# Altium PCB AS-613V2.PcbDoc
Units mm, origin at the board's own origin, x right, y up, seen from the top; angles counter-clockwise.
Board outline 32 x 30 mm, 4 copper layers (Top Layer, Layer 1, Layer 2, Bottom Layer), stack 1.18 mm thick; 70 components, 43 nets, 483 pads, 357 vias.
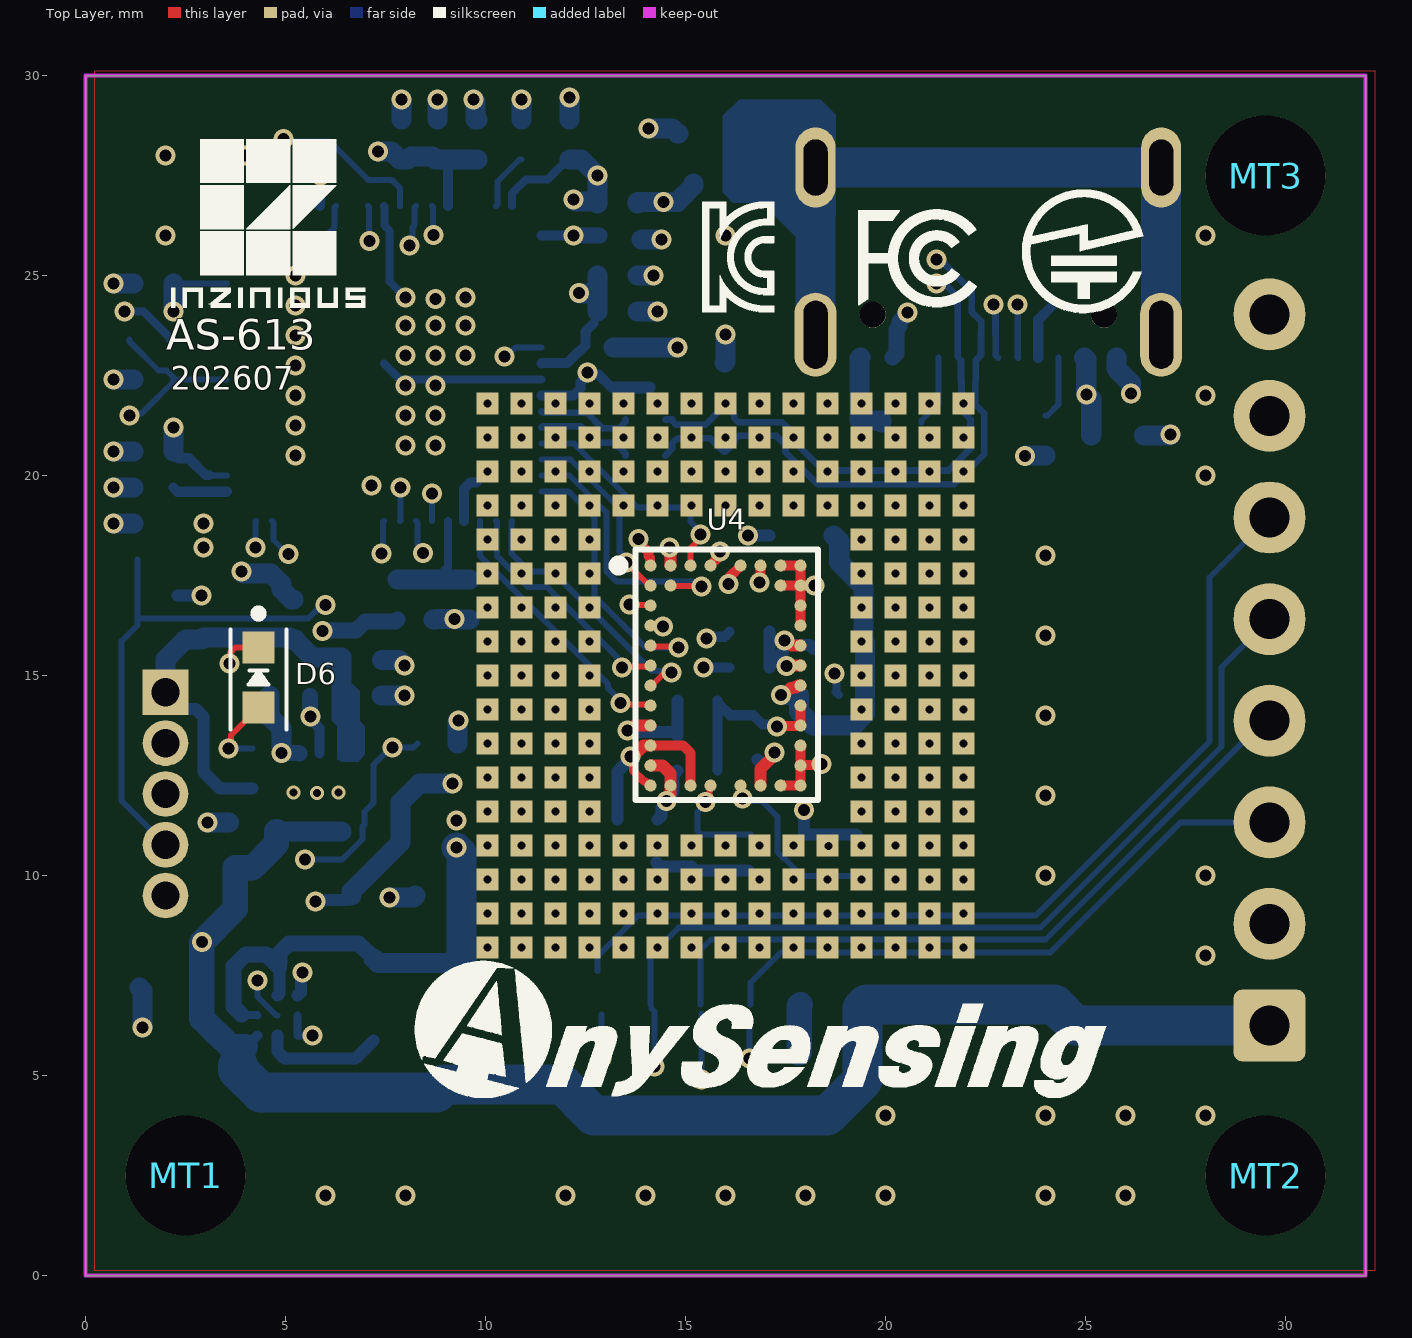
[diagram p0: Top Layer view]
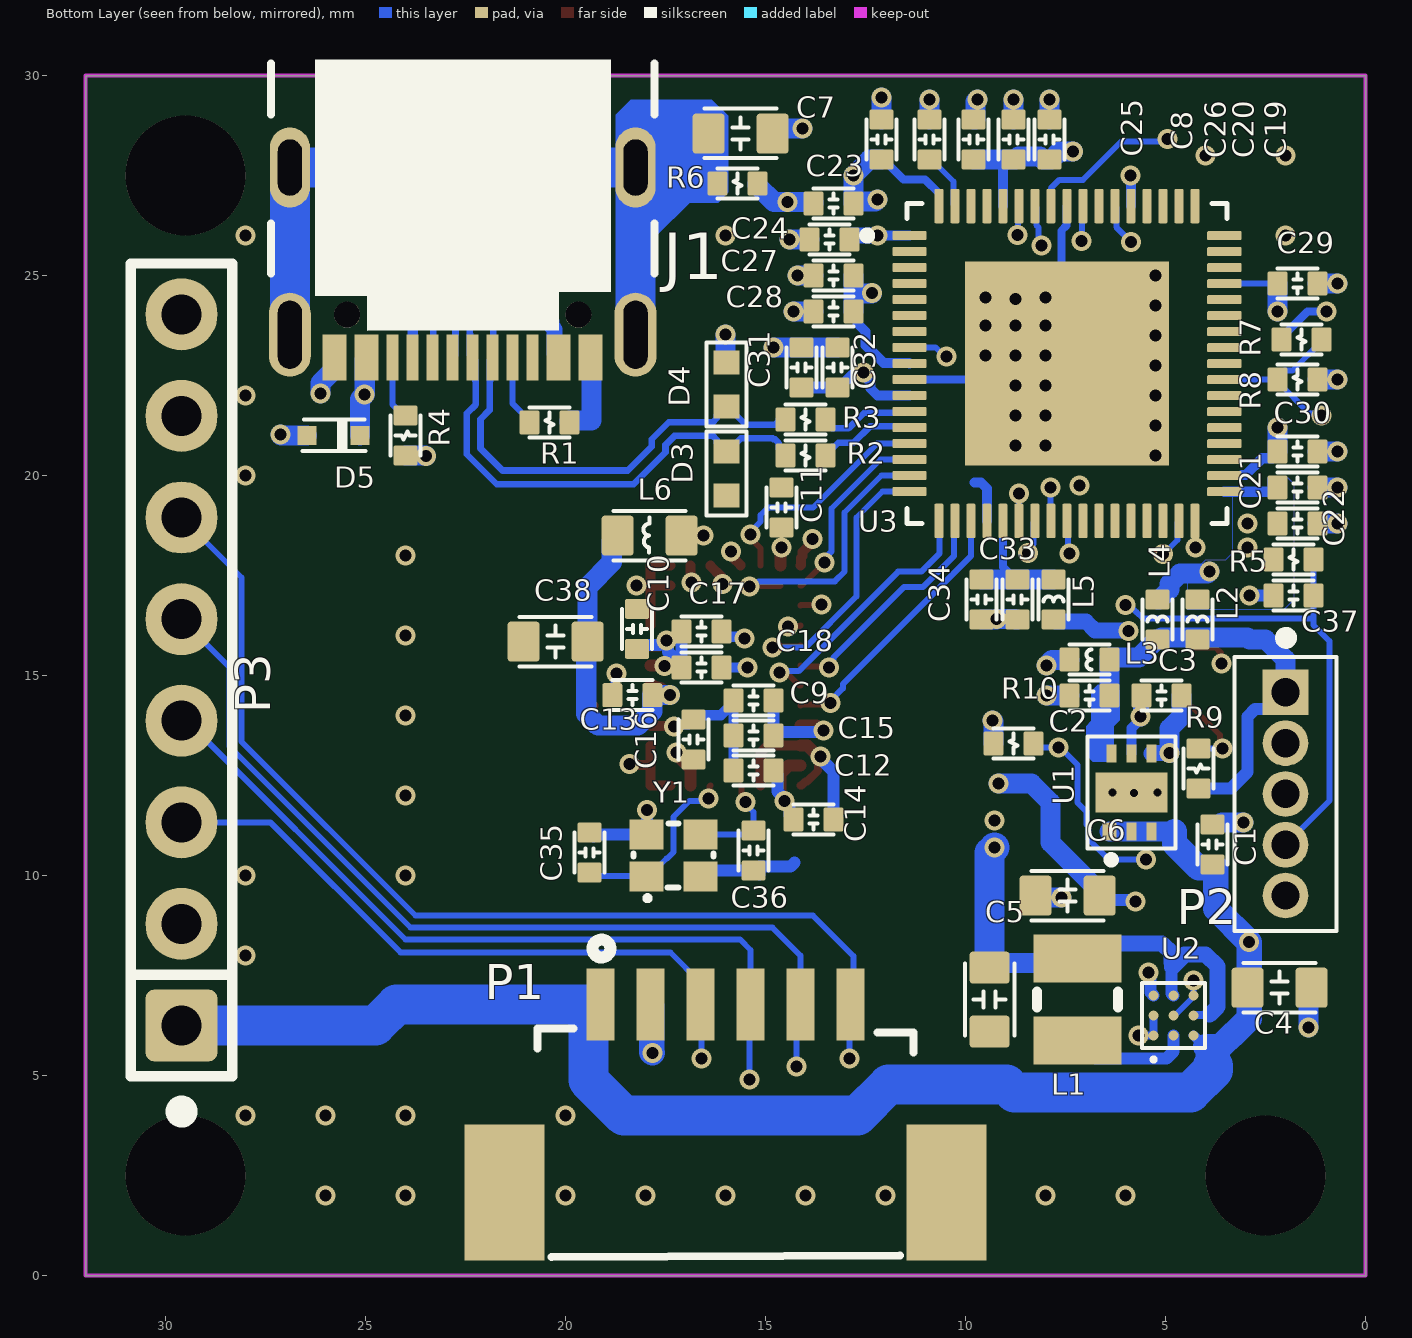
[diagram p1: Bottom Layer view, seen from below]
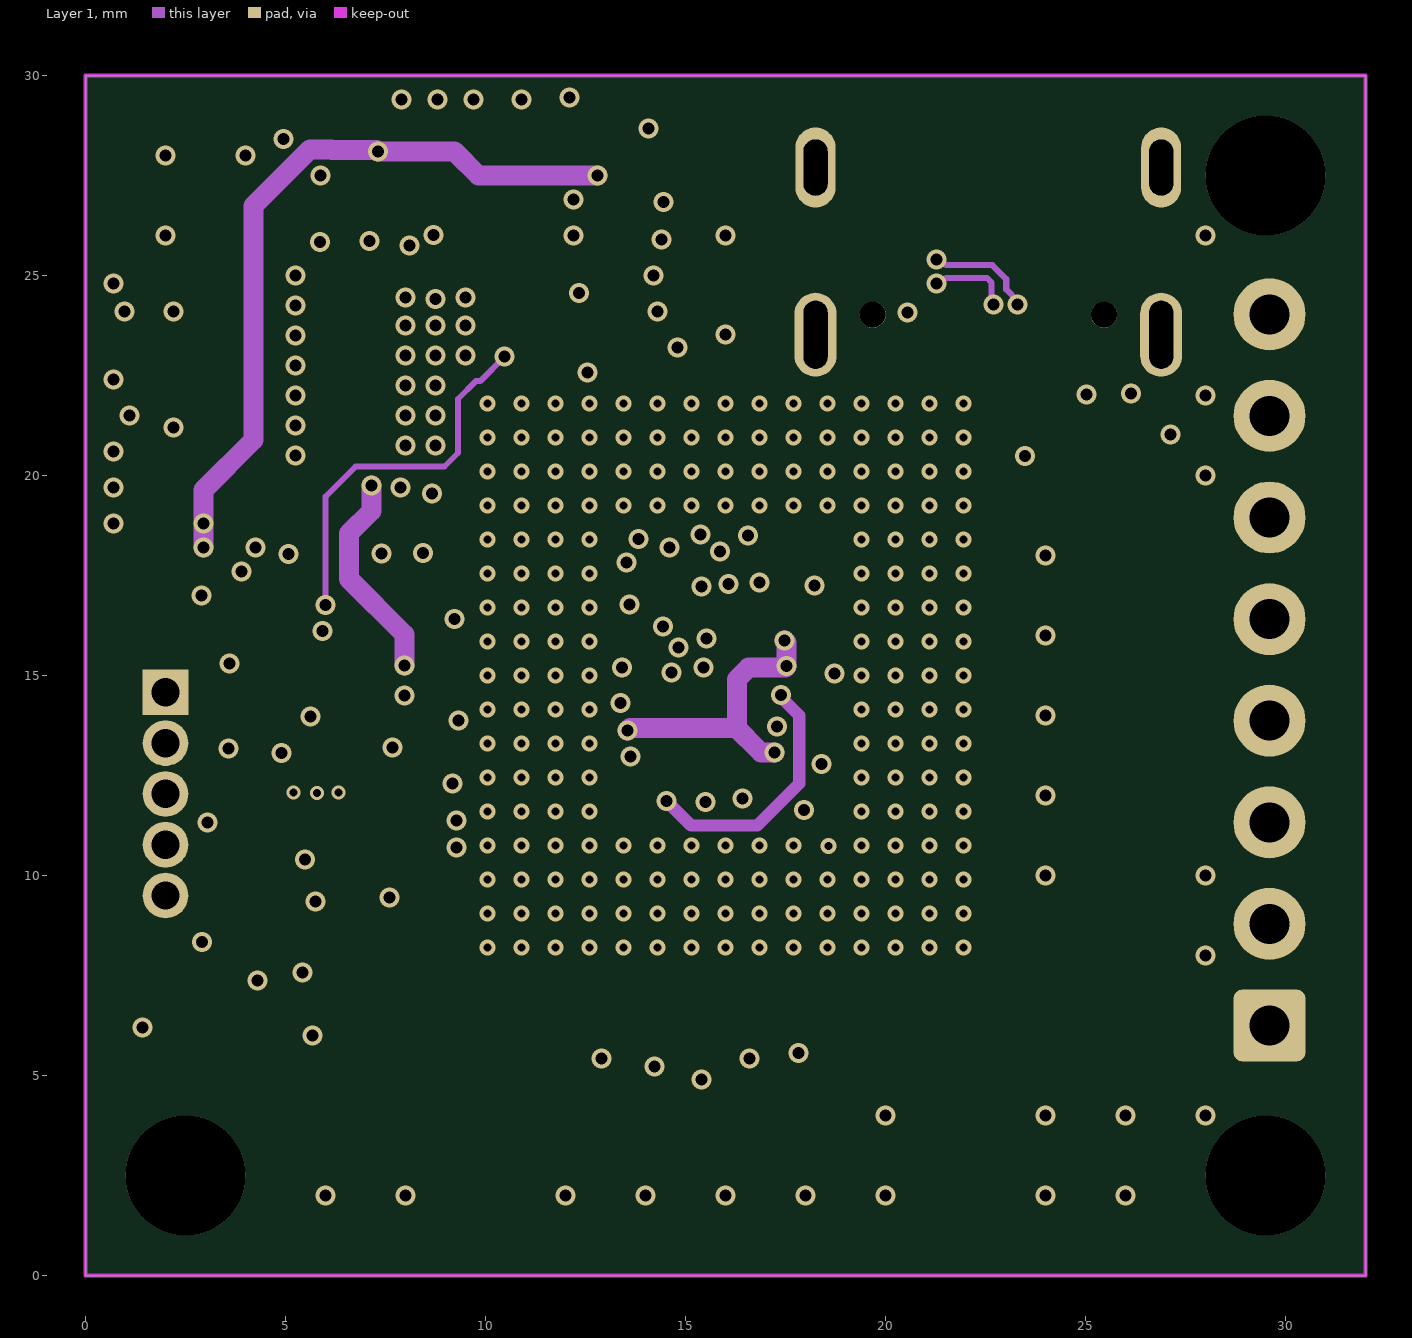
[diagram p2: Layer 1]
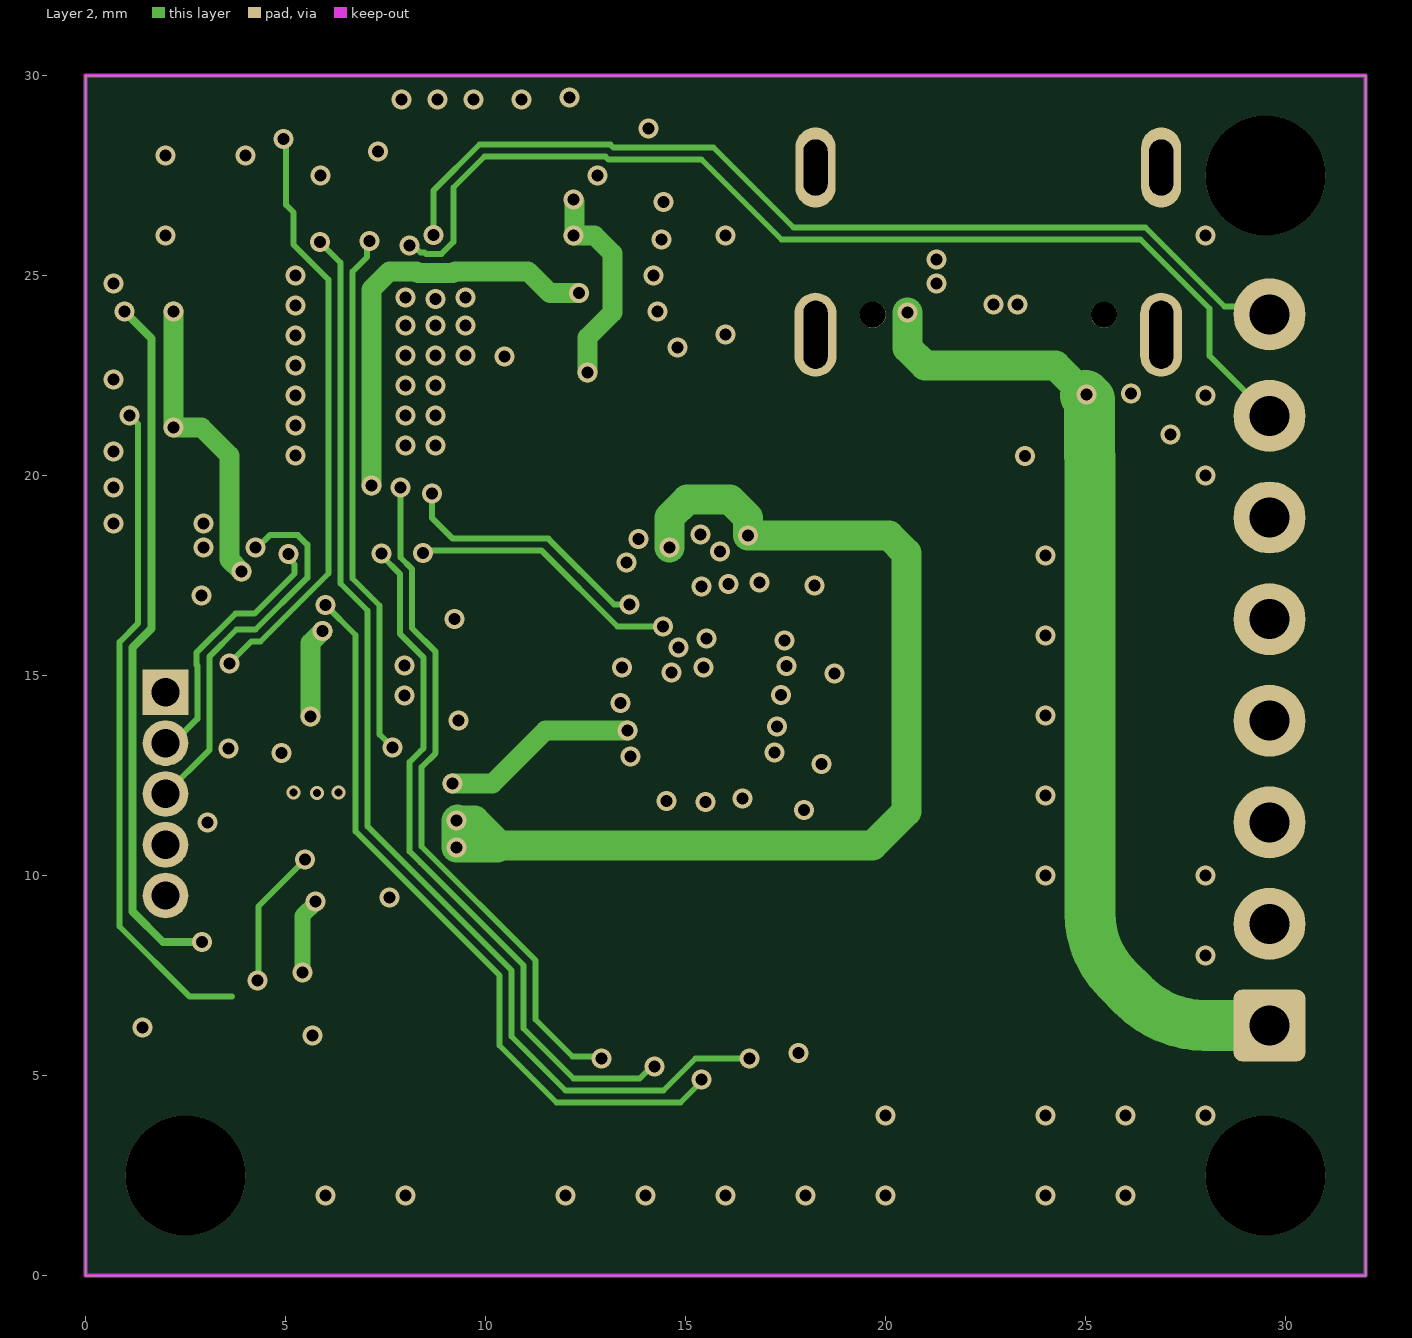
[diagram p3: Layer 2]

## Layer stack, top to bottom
Top Solder: solder mask 0.0102, Solder Resist, Dk 3.5
Top Layer: signal copper 0.0356
Dielectric 2: prepreg 0.0711, PP-006, Dk 4.1
Layer 1: signal copper 0.035
Dielectric 1: dielectric 0.897, FR-4, Dk 4.8
Layer 2: signal copper 0.035
Dielectric 3: prepreg 0.0711, PP-006, Dk 4.1
Bottom Layer: signal copper 0.0356
Bottom Solder: solder mask 0.0102, Solder Resist, Dk 3.5

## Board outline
0,0 0,30 32,30 32,0

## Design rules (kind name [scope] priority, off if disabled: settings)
AssemblyTestPointUsage [All] p1 off:
AssemblyTestpoint [All] p1 off: testpointundercomponent=TRUE minsize=1.016 maxsize=2.54 preferedsize=1.524 minholesize=0 maxholesize=1.016 preferedholesize=0.813 testpointgrid=0.025 usegrid=TRUE gridtolerance=0 allowsidetop=TRUE allowsidebottom=TRUE
BoardOutlineClearance BoardOutlineClearance_1 [OnLayer('Layer 2')] p1 off: gap=0.7 ignorepadtopadclearanceinfootprint=FALSE
BoardOutlineClearance [All] p2: gap=0.3 ignorepadtopadclearanceinfootprint=FALSE
Clearance Clearance_1 [InComponent('U2')] p1: gap=0.1 ignorepadtopadclearanceinfootprint=TRUE except(0.2: Arc-Poly Track-Poly SMDPad-Poly THPad-Poly Via-Poly Fill-Poly Poly-Poly)
Clearance Clearance_diff [InAnyDifferentialPair] p2: gap=0.1 ignorepadtopadclearanceinfootprint=TRUE except(0.33: Arc-Poly Track-Poly SMDPad-Poly THPad-Poly Via-Poly Fill-Poly Poly-Poly)
Clearance [All] p3: gap=0.15 ignorepadtopadclearanceinfootprint=TRUE except(0.2: Arc-Poly Track-Poly SMDPad-Poly THPad-Poly Via-Poly Fill-Poly Poly-Poly)
ComponentClearance [All] p1 off: gap=0.254 collisioncheckmode=3 verticalgap=0.254 showdistances=FALSE
DiffPairsRouting DiffPairsRouting_100d [InDifferentialPairClass('100D')] p1: maxlimit=0.203 minlimit=0.178 mostfreqgap=0.203 toplayer_maxgap=0.178 toplayer_prefgap=0.178 toplayer_minwidth=0.127 toplayer_maxwidth=0.127 toplayer_prefwidth=0.127 midlayer1_mingap=0.203 midlayer1_minwidth=0.135 midlayer1_maxwidth=0.135 midlayer1_prefwidth=0.135 midlayer2_mingap=0.203 midlayer2_minwidth=0.135 midlayer2_maxwidth=0.135 midlayer2_prefwidth=0.135 bottomlayer_maxgap=0.178 bottomlayer_prefgap=0.178 bottomlayer_minwidth=0.127 bottomlayer_maxwidth=0.127 bottomlayer_prefwidth=0.127 maxuncoupledlength=12.7
DiffPairsRouting DiffPairsRouting_90d [InNetClass('90d')] p2: maxlimit=0.178 minlimit=0.165 mostfreqgap=0.178 toplayer_mingap=0.178 toplayer_minwidth=0.165 toplayer_maxwidth=0.165 toplayer_prefwidth=0.165 midlayer1_maxgap=0.165 midlayer1_prefgap=0.165 midlayer1_minwidth=0.152 midlayer1_maxwidth=0.152 midlayer1_prefwidth=0.152 midlayer2_maxgap=0.165 midlayer2_prefgap=0.165 midlayer2_minwidth=0.152 midlayer2_maxwidth=0.152 midlayer2_prefwidth=0.152 bottomlayer_mingap=0.178 bottomlayer_minwidth=0.165 bottomlayer_maxwidth=0.165 bottomlayer_prefwidth=0.165 maxuncoupledlength=12.7
FabricationTestPointUsage [All] p1 off: valid=0 allowmultiple=FALSE
FabricationTestpoint [All] p1 off: side=3 testpointundercomponent=TRUE minsize=1.016 maxsize=2.54 preferedsize=1.524 minholesize=0 maxholesize=1.016 preferedholesize=0.813 testpointgrid=0.025 allowsidetop=TRUE allowsidebottom=TRUE usegrid=TRUE gridtolerance=0
Height [All] p1 off: minheight=0 maxheight=25.4 prefheight=12.7
HoleSize [All] p1 off: absolutevalues=TRUE maxlimit=2.54 minlimit=0.025 maxpercent=80.000 minpercent=20.000
HoleToHoleClearance [All] p1 off: gap=0.254 allowstackedmicrovias=TRUE
LayerPairs [All] p1 off: enforce=TRUE
MinimumSolderMaskSliver [All] p1 off: minsoldermaskwidth=0.254
NetAntennae [All] p1 off: netantennaetolerance=0
PlaneConnect [All] p1: planeconnectstyle=Direct reliefexpansion=0.508 reliefentries=4 reliefconductorwidth=0.254 reliefairgap=0.254
PolygonConnect [All] p1: connectstyle=Direct reliefconductorwidth=0.254 reliefentries=4 polygonreliefangle="90 Angle" airgapwidth=0.254
RoutingVias [All] p1: holewidth=0.711 width=1.27 viastyle="Through Hole" minholewidth=0.711 minwidth=1.27 maxholewidth=0.711 maxwidth=1.27 useviatemplates=TRUE viatemplateguid#1={31C3CD5B-DCC8-4F60-9EBC-FCC5245C43CC} viatemplatename#1=v50h30m0mx0
SilkToSilkClearance [All] p1 off: silktosilkclearance=0.254
SilkToSolderMaskClearance [IsPad] p1 off: minsilkscreentomaskgap=0.254 clearancetoexposedcopper=TRUE
SolderMaskExpansion [All] p1: expansion=0.102 istentingtop=FALSE
SupplyNets "Schematic Supply Nets" [InNet('VCC_1V8RF')] p1: voltage=0.000
SupplyNets "Schematic Supply Nets_11" [InNet('VCC_1V8R')] p2: voltage=0.000
SupplyNets "Schematic Supply Nets_10" [InNet('VCC_3V3M')] p3: voltage=0.000
SupplyNets "Schematic Supply Nets_9" [InNet('VCC_1V2R')] p4: voltage=0.000
SupplyNets "Schematic Supply Nets_8" [InNet('GND')] p5: voltage=0.000
SupplyNets "Schematic Supply Nets_7" [InNet('VCC_3V3MA')] p6: voltage=0.000
SupplyNets "Schematic Supply Nets_5" [InNet('VCC_5V')] p7: voltage=0.000
SupplyNets "Schematic Supply Nets_4" [InNet('VCC_1V8M')] p8: voltage=0.000
SupplyNets "Schematic Supply Nets_3" [InNet('VCC_3V3MM')] p9: voltage=0.000
SupplyNets "Schematic Supply Nets_2" [InNet('VCC_3V3MN')] p10: voltage=0.000
SupplyNets "Schematic Supply Nets_1" [InNet('VCC_1V8MM')] p11: voltage=0.000
Width [All] p1: maxlimit=3 minlimit=0.15 preferedwidth=0.15
15 further rules are at their usual default settings.

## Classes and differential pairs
net class 90d: USB_N USB_P USBD_N USBD_P
differential pair USBD: +USBD_P -USBD_N
differential pair USB: +USB_P -USB_N

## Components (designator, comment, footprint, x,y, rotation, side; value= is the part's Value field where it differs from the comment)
C1 "Cap Semi" "CAP 0402/1005" 3.825,10.775 r270 bottom value=1uF
C2 "Cap Semi" "CAP 0402/1005" 6.9,14.5 r180 bottom value=1uF
C3 "Cap Semi" "CAP 0402/1005" 5.1,14.5 r0 bottom value=1uF
C4 "Cap Semi" "CAP 0603/1608" 2.15,7.196 r0 bottom value=4.7uF
C5 "Cap Semi" "CAP 0603/1608" 9.4,6.9 r90 bottom value=10uF
C6 "Cap Semi" "CAP 0603/1608" 7.45,9.5 r180 bottom value=2.2uF
C7 "Cap Semi" "CAP 0603/1608" 15.625,28.55 r0 bottom value=4.7uF
C8 "Cap Semi" "CAP 0402/1005" 10.9,28.4 r270 bottom value=4.7uF
C9 "Cap Semi" "CAP 0402/1005" 15.3,14.375 r180 bottom value=10uF
C10 "Cap Semi" "CAP 0402/1005" 18.212,16.164 r270 bottom value=10uF
C11 "Cap Semi" "CAP 0402/1005" 14.6,19.2 r270 bottom value=1uF
C12 "Cap Semi" "CAP 0402/1005" 15.3,12.625 r180 bottom value=1uF
C13 "Cap Semi" "CAP 0402/1005" 18.332,14.508 r180 bottom value=1uF
C14 "Cap Semi" "CAP 0402/1005" 13.8,11.4 r0 bottom value=1uF
C15 "Cap Semi" "CAP 0402/1005" 15.3,13.5 r180 bottom value=1uF
C16 "Cap Semi" "CAP 0402/1005" 16.8,13.4 r270 bottom value=1uF
C17 "Cap Semi" "CAP 0402/1005" 16.6,16.1 r0 bottom value=1uF
C18 "Cap Semi" "CAP 0402/1005" 16.6,15.2 r0 bottom value=1uF
C19 "Cap Semi" "CAP 0402/1005" 7.9,28.4 r270 bottom value=100nF
C20 "Cap Semi" "CAP 0402/1005" 8.8,28.4 r270 bottom value=1uF
C21 "Cap Semi" "CAP 0402/1005" 1.7,19.7 r0 bottom value=100nF
C22 "Cap Semi" "CAP 0402/1005" 1.7,18.8 r0 bottom value=1uF
C23 "Cap Semi" "CAP 0402/1005" 13.3,26.8 r180 bottom value=100nF
C24 "Cap Semi" "CAP 0402/1005" 13.4,25.9 r180 bottom value=1uF
C25 "Cap Semi" "CAP 0402/1005" 12.1,28.4 r270 bottom value=100nF
C26 "Cap Semi" "CAP 0402/1005" 9.8,28.4 r270 bottom value=10uF
C27 "Cap Semi" "CAP 0402/1005" 13.3,25 r180 bottom value=100nF
C28 "Cap Semi" "CAP 0402/1005" 13.3,24.1 r180 bottom value=10uF
C29 "Cap Semi" "CAP 0402/1005" 1.7,24.8 r0 bottom value=100nF
C30 "Cap Semi" "CAP 0402/1005" 1.7,20.6 r0 bottom value=10uF
C31 "Cap Semi" "CAP 0402/1005" 14.1,22.7 r270 bottom value=100nF
C32 "Cap Semi" "CAP 0402/1005" 13.2,22.7 r270 bottom value=1uF
C33 "Cap Semi" "CAP 0402/1005" 8.7,16.9 r90 bottom value=100nF
C34 "Cap Semi" "CAP 0402/1005" 9.6,16.9 r90 bottom value=1uF
C35 "Cap Semi" "CAP 0402/1005" 19.4,10.575 r270 bottom value=10pF
C36 "Cap Semi" "CAP 0402/1005" 15.3,10.624 r90 bottom value=10pF
C37 "Cap Semi" "CAP 0402/1005" 1.8,17 r180 bottom value=100nF
C38 "Cap Semi" "CAP 0603/1608" 20.25,15.85 r180 bottom value=10uF
D3 "GG0402055R042P" "TVS 0402/1005 - BI" 15.975,20.05 r90 bottom
D4 "GG0402055R042P" "TVS 0402/1005 - BI" 15.975,22.275 r270 bottom
D5 "ESD5Z5.0T1G" "SOD523 - 21" 25.8,21 r180 bottom
D6 "GREEN" "LED 0603/1608 RED" 4.325,14.95 r90 top
J1 "USB4105-GF-A" "CON/ USB/ GCT_USB4105-GF-A" 22.57,25.323 r0 bottom locked
L1 "VLS252010HBX-2R2M-1" "IND 2520" 7.2,6.9 r90 bottom value=2.2µH
L2 "MMZ1005S102CT000" "FER 0402/1005" 4.2,16.4 r90 bottom
L3 "MMZ1005S102CT000" "FER 0402/1005" 6.9,15.4 r0 bottom
L4 "MMZ1005S102CT000" "FER 0402/1005" 5.2,16.4 r90 bottom
L5 "MMZ1005S102CT000" "FER 0402/1005" 7.8,16.9 r90 bottom
L6 "BLM18PG121SN1D" "FER 0603/1608" 17.9,18.5 r180 bottom
MT1 "MOUNT HOLE" "MT-3 /HOLE"#1 34.804,1.503 r0 top
MT2 "MOUNT HOLE" "MT-3 /HOLE"#2 39.079,1.503 r0 top
MT3 "MOUNT HOLE" "MT-3 /HOLE"#3 43.355,1.503 r0 top
P1 "12507WR-H06G" 12507WR-H06G 16,6.774 r180 bottom locked
P2 "HEADER/12.7mm" "Pin Header 1x5 1.27mm" 2,12.04 r270 bottom
P3 "HEADER/2.54mm" "PIN HEADER 1X8 TH PITCH 2.54MM" 29.6,6.25 r90 bottom
R1 "Res3" "RES 0402/1005" 20.4,21.325 r180 bottom value=5.1K
R2 "Res3" "RES 0402/1005" 14,20.5 r180 bottom value=22R
R3 "Res3" "RES 0402/1005" 14,21.4 r180 bottom value=22R
R4 "Res3" "RES 0402/1005" 24,21 r270 bottom value=5.1K
R5 "Res3" "RES 0402/1005" 1.8,17.9 r180 bottom value=4.7K
R6 "Res3" "RES 0402/1005" 15.7,27.3 r180 bottom value=4.7K
R7 "Res3" "RES 0402/1005" 1.6,23.4 r180 bottom value=47K
R8 "Res3" "RES 0402/1005" 1.7,22.4 r180 bottom value=47K
R9 "Res3" "RES 0402/1005" 4.175,12.675 r90 bottom value=330R
R10 "Res3" "RES 0402/1005" 8.8,13.3 r0 bottom value=10K
U1 "VRD1833MLX" "LLP-6 / L2.0-W1.8-P0.50-BL-EP" 5.875,12.075 r180 bottom
U2 "LM3687TL-1812/NOPB" "DSBGA-9 / BGA50P147X147" 4.8,6.5 r90 bottom
U3 "CY8C6148LQI-S2F02" "QFN-68 /QFN40P800X800X100-69N" 7.465,22.8 r180 bottom
U4 "BGT60CUTR13AIP" "BGT60CUTR13AIP / IFX- PG-VF2BGA-38-1" 16,15 r0 top locked
Y1 "80MHz/2016" XTAL/2016 17.975,9.975 r180 bottom value=E1SB80E00000GE

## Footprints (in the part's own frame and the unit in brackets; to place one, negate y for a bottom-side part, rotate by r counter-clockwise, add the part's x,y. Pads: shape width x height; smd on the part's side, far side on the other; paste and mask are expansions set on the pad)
12507WR-H06G [mm]
  rect 0.7x1.8 smd: 1(-3.125,0) 2(-1.875,0) 3(-0.625,0) 4(0.625,0) 5(1.875,0) 6(3.125,0)
  rect 2x3.4 smd: H(-5.525,-4.7) H(5.525,-4.7)
  silkscreen extent -4.7,-6.32 4.7,1.62, body extent -6.2,-6.38 6.23,0.33, height 2.5
"BGT60CUTR13AIP / IFX- PG-VF2BGA-38-1" [mm] "BGA,0.50mm pitch,rect.;38 pin,8 columns X 12 rows,4.30mm X 6.05mm X 0.91mm H"
  round 0.3 smd paste+0 mask+0: A1(-1.875,2.75) A2(-1.375,2.75) A3(-0.875,2.75) A4(-0.375,2.75) A5(0.375,2.75) A6(0.875,2.75) A7(1.375,2.75) A8(1.875,2.75) B1(-1.875,2.25) B2(-1.375,2.25) B7(1.375,2.25) B8(1.875,2.25) C1(-1.875,1.75) C8(1.875,1.75) D1(-1.875,1.25) D8(1.875,1.25) E1(-1.875,0.75) E8(1.875,0.75) F1(-1.875,0.25) F8(1.875,0.25) G1(-1.875,-0.25) G8(1.875,-0.25) H1(-1.875,-0.75) H8(1.875,-0.75) J1(-1.875,-1.25) J8(1.875,-1.25) K1(-1.875,-1.75) K8(1.875,-1.75) L1(-1.875,-2.25) L8(1.875,-2.25) M1(-1.875,-2.75) M2(-1.375,-2.75) M3(-0.875,-2.75) M4(-0.375,-2.75) M5(0.375,-2.75) M6(0.875,-2.75) M7(1.375,-2.75) M8(1.875,-2.75)
  rect 0.55x0.55 smd paste-2539.97 mask+0: H(-5.95,-6.8) H(-5.95,-5.95) H(-5.95,-5.1) H(-5.95,-4.25) H(-5.95,-3.4) H(-5.95,-2.55) H(-5.95,-1.7) H(-5.95,-0.85) H(-5.95,0) H(-5.95,0.85) H(-5.95,1.7) H(-5.95,2.55) H(-5.95,3.4) H(-5.95,4.25) H(-5.95,5.1) H(-5.95,5.95) H(-5.95,6.8) H(-5.1,-6.8) H(-5.1,-5.95) H(-5.1,-5.1) H(-5.1,-4.25) H(-5.1,-3.4) H(-5.1,-2.55) H(-5.1,-1.7) H(-5.1,-0.85) H(-5.1,0) H(-5.1,0.85) H(-5.1,1.7) H(-5.1,2.55) H(-5.1,3.4) H(-5.1,4.25) H(-5.1,5.1) H(-5.1,5.95) H(-5.1,6.8) H(-4.25,-6.8) H(-4.25,-5.95) H(-4.25,-5.1) H(-4.25,-4.25) H(-4.25,-3.4) H(-4.25,-2.55) H(-4.25,-1.7) H(-4.25,-0.85) H(-4.25,0) H(-4.25,0.85) H(-4.25,1.7) H(-4.25,2.55) H(-4.25,3.4) H(-4.25,4.25) H(-4.25,5.1) H(-4.25,5.95) H(-4.25,6.8) H(-3.4,-6.8) H(-3.4,-5.95) H(-3.4,-5.1) H(-3.4,-4.25) H(-3.4,4.25) H(-3.4,5.1) H(-3.4,5.95) H(-3.4,6.8) H(-3.4,-3.4) H(-3.4,-2.55) H(-3.4,-1.7) H(-3.4,-0.85) H(-3.4,0) H(-3.4,0.85) H(-3.4,1.7) H(-3.4,2.55) H(-3.4,3.4) H(-2.55,-6.8) H(-2.55,-6.8) H(-2.55,-5.95) H(-2.55,-5.95) H(-2.55,-5.1) H(-2.55,-5.1) H(-2.55,-4.25) H(-2.55,-4.25) H(-2.55,4.25) H(-2.55,5.1) H(-2.55,5.95) H(-2.55,5.95) H(-2.55,6.8) H(-2.55,6.8) H(-1.7,-6.8) H(-1.7,-5.95) H(-1.7,-5.1) H(-1.7,-4.25) H(-1.7,4.25) H(-1.7,5.1) H(-1.7,5.95) H(-1.7,6.8) H(-0.85,-6.8) H(-0.85,-5.95) H(-0.85,-5.1) H(-0.85,-4.25) H(-0.85,4.25) H(-0.85,5.1) H(-0.85,5.95) H(-0.85,6.8) H(0,-6.8) H(0,-5.95) H(0,-5.1) H(0,-4.25) H(0,4.25) H(0,5.1) H(0,5.95) H(0,6.8) H(0.85,-6.8) H(0.85,-5.95) H(0.85,-5.1) H(0.85,-4.25) H(0.85,4.25) H(0.85,5.1) H(0.85,5.95) H(0.85,6.8) H(1.7,-6.8) H(1.7,-5.95) H(1.7,-5.1) H(1.7,-4.25) H(1.7,4.25) H(1.7,5.1) H(1.7,5.95) H(1.7,6.8) H(2.55,-6.8) H(2.55,-5.95) H(2.55,-5.1) H(2.55,-4.25) H(2.55,4.25) H(2.55,5.1) H(2.55,5.95) H(2.55,6.8) H(3.4,-6.8) H(3.4,-5.95) H(3.4,-5.1) H(3.4,-4.25) H(3.4,-3.4) H(3.4,-2.55) H(3.4,-1.7) H(3.4,-0.85) H(3.4,0) H(3.4,0.85) H(3.4,1.7) H(3.4,2.55) H(3.4,3.4) H(3.4,4.25) H(3.4,5.1) H(3.4,5.95) H(3.4,6.8) H(4.25,-6.8) H(4.25,-5.95) H(4.25,-5.1) H(4.25,-4.25) H(4.25,-3.4) H(4.25,-2.55) H(4.25,-1.7) H(4.25,-0.85) H(4.25,0) H(4.25,0.85) H(4.25,1.7) H(4.25,2.55) H(4.25,3.4) H(4.25,4.25) H(4.25,5.1) H(4.25,5.95) H(4.25,6.8) H(5.1,-6.8) H(5.1,-5.95) H(5.1,-5.1) H(5.1,-4.25) H(5.1,-3.4) H(5.1,-2.55) H(5.1,-1.7) H(5.1,-0.85) H(5.1,0) H(5.1,0.85) H(5.1,1.7) H(5.1,2.55) H(5.1,3.4) H(5.1,4.25) H(5.1,5.1) H(5.1,5.95) H(5.1,6.8) H(5.95,-6.8) H(5.95,-5.95) H(5.95,-5.1) H(5.95,-4.25) H(5.95,-3.4) H(5.95,-2.55) H(5.95,-1.7) H(5.95,-0.85) H(5.95,0) H(5.95,0.85) H(5.95,1.7) H(5.95,2.55) H(5.95,3.4) H(5.95,4.25) H(5.95,5.1) H(5.95,5.95) H(5.95,6.8)
  silkscreen extent -2.8,-3.11 2.31,3.15, body extent -2.15,-3.02 2.15,3.03, height 0.87
"CAP 0402/1005" [mm] "Chip Capacitor, 2-Leads, Body 1.02x0.51mm, IPC Medium Density"
  rrect20% 0.5x0.6 smd mask+0.051: 1(-0.5,0) 2(0.5,0)
  silkscreen extent -0.5,-0.38 0.5,0.38, body extent -0.49,-0.25 0.51,0.27, height 0.52
"CAP 0603/1608" [mm] "Chip Capacitor, 2-Leads, Body 1.60x0.80mm, IPC Medium Density"
  rrect20% 0.8x1 smd mask+0.051: 1(-0.8,0) 2(0.8,0)
  silkscreen extent -0.9,-0.62 0.9,0.62, body extent -0.8,-0.41 0.8,0.41, height 0.82
"CON/ USB/ GCT_USB4105-GF-A" [mm]
  oval 1x2 hole 0.6 slot 1.4 at 90 deg: 1(-4.32,-2.377) 4(4.32,-2.377)
  oval 1.05x2.1 hole 0.6 slot 1.7 at 90 deg: 2(-4.32,1.803) 3(4.32,1.803)
  rect 0.6x1.15 smd: A1-B12(-3.2,2.378) A4-B9(-2.4,2.378) B1-A12(3.2,2.378) B4-A9(2.4,2.378)
  rect 0.3x1.15 smd: A5(-1.25,2.378) A6(-0.25,2.378) A7(0.25,2.378) A8(1.25,2.378) B5(1.75,2.378) B6(0.75,2.378) B7(-0.75,2.378) B8(-1.75,2.378)
  round 0.65 hole 0.65 unplated: ""(-2.89,1.303) ""(2.89,1.303)
  silkscreen extent -4.79,-5.08 4.79,1.7, body extent -4.79,-5.09 4.79,2.62, height 3.31
"DSBGA-9 / BGA50P147X147" [mm]
  round 0.245 smd paste-1 mask+0: A1(-0.5,0.5) A2(0,0.5) A3(0.5,0.5) B1(-0.5,0) B2(0,0) B3(0.5,0) C1(-0.5,-0.5) C2(0,-0.5) C3(0.5,-0.5)
  silkscreen extent -1.15,-0.79 0.81,0.79, body extent -0.81,-0.79 0.81,0.79, height 0.63
"FER 0402/1005" [mm] "Chip Ferrite, 2-Leads, Body 1.02x0.51mm, IPC Medium Density"
  rrect20% 0.5x0.6 smd mask+0.051: 1(-0.5,0) 2(0.5,0)
  silkscreen extent -0.5,-0.38 0.5,0.38, body extent -0.55,-0.26 0.45,0.26, height 0.52
"FER 0603/1608" [mm] "Chip Ferrite, 2-Leads, Body 1.60x0.80mm, IPC Medium Density"
  rrect20% 0.8x1 smd mask+0.051: 1(-0.8,0) 2(0.8,0)
  silkscreen extent -0.9,-0.62 0.9,0.62, body extent -0.8,-0.41 0.8,0.41, height 0.82
"IND 2520" [mm]
  rect 1.2x2.2 smd: 1(-1.028,0) 2(1.028,0)
  silkscreen extent -0.2,-1.02 0.2,1.02, body extent -1.28,-0.95 1.22,0.95, height 1.1
"LED 0603/1608 RED" [mm] "Chip Diode, 2-Leads, Body 1.60x0.80mm, IPC Medium Density"
  rect 0.8x0.8 smd: 1(-0.75,0) 2(0.75,0)
  silkscreen extent -1.3,-0.7 1.65,0.7, body extent -0.8,-0.4 0.8,0.4, height 0.53
"LLP-6 / L2.0-W1.8-P0.50-BL-EP" [mm]
  rect 0.35x0.45 smd paste+0 mask+0.051: 1(-0.525,-0.975)
  rect 0.25x0.45 smd paste+0 mask+0.051: 2(0.025,-0.975) 3(0.525,-0.975) 4(0.525,0.975) 5(0.025,0.975) 6(-0.475,0.975)
  rect 1.8x1 smd paste+0 mask+0.051: 7(0.025,0)
  silkscreen extent -1.07,-1.74 1.12,1.4, body extent -0.9,-1 0.9,1, height 0.6
"MT-3 /HOLE"#1 [mm] "Mount Hole 4mm"
  round 3 hole 3 mask+0: 1(-32.304,0.997)
"MT-3 /HOLE"#2 [mm] "Mount Hole 4mm"
  round 3 hole 3 mask+0: 1(-9.579,0.997)
"MT-3 /HOLE"#3 [mm] "Mount Hole 4mm"
  round 3 hole 3 mask+0: 1(-13.855,25.997)
"Pin Header 1x5 1.27mm" [mil]
  rect 45x45 hole 27.95: 1(-100,0)
  round 45 hole 27.95: 2(-50,0) 3(0,0) 4(50,0) 5(100,0)
  silkscreen extent -158,-50 135,50
"PIN HEADER 1X8 TH PITCH 2.54MM" [mm] "PinHeader 1x8 TH Pitch 2.54mm"
  rrect25% 1.8x1.8 hole 1: 1(0,0)
  round 1.8 hole 1: 2(2.54,0) 3(5.08,0) 4(7.62,0) 5(10.16,0) 6(12.7,0) 7(15.24,0) 8(17.78,0)
  silkscreen extent -2.3,-1.27 19.05,1.27, body extent -1.27,-1.27 19.05,1.27, height 9.5
"QFN-68 /QFN40P800X800X100-69N" [mm]
  rrect25% 0.86x0.22 smd: 1(-3.935,3.2) 2(-3.935,2.8) 3(-3.935,2.4) 4(-3.935,2) 5(-3.935,1.6) 6(-3.935,1.2) 7(-3.935,0.8) 8(-3.935,0.4) 9(-3.935,0) 10(-3.935,-0.4) 11(-3.935,-0.8) 12(-3.935,-1.2) 13(-3.935,-1.6) 14(-3.935,-2) 15(-3.935,-2.4) 16(-3.935,-2.8) 17(-3.935,-3.2) 35(3.935,-3.2) 36(3.935,-2.8) 37(3.935,-2.4) 38(3.935,-2) 39(3.935,-1.6) 40(3.935,-1.2) 41(3.935,-0.8) 42(3.935,-0.4) 43(3.935,0) 44(3.935,0.4) 45(3.935,0.8) 46(3.935,1.2) 47(3.935,1.6) 48(3.935,2) 49(3.935,2.4) 50(3.935,2.8) 51(3.935,3.2)
  rrect25% 0.22x0.86 smd: 18(-3.2,-3.935) 19(-2.8,-3.935) 20(-2.4,-3.935) 21(-2,-3.935) 22(-1.6,-3.935) 23(-1.2,-3.935) 24(-0.8,-3.935) 25(-0.4,-3.935) 26(0,-3.935) 27(0.4,-3.935) 28(0.8,-3.935) 29(1.2,-3.935) 30(1.6,-3.935) 31(2,-3.935) 32(2.4,-3.935) 33(2.8,-3.935) 34(3.2,-3.935) 52(3.2,3.935) 53(2.8,3.935) 54(2.4,3.935) 55(2,3.935) 56(1.6,3.935) 57(1.2,3.935) 58(0.8,3.935) 59(0.4,3.935) 60(0,3.935) 61(-0.4,3.935) 62(-0.8,3.935) 63(-1.2,3.935) 64(-1.6,3.935) 65(-2,3.935) 66(-2.4,3.935) 67(-2.8,3.935) 68(-3.2,3.935)
  rect 5.1x5.1 smd paste-4: 69(0,0)
  silkscreen extent -5.09,-4 4,4, body extent -4.05,-4.05 4.05,4.05, height 0.85
"RES 0402/1005" [mm] "Chip Resistor, 2-Leads, Body 1.0x0.5mm, IPC Medium Density"
  rrect20% 0.5x0.6 smd mask+0.051: 1(-0.5,0) 2(0.5,0)
  silkscreen extent -0.5,-0.38 0.5,0.38, body extent -0.5,-0.24 0.5,0.26, height 0.35
"SOD523 - 21" [mm]
  rect 0.48x0.48 smd mask+0.051: 1(0.66,0) 2(-0.66,0)
  silkscreen extent -0.77,-0.42 0.8,0.4, body extent -0.77,-0.4 0.83,0.4, height 0.65
"TVS 0402/1005 - BI" [mm] "Chip Capacitor, 2-Leads, Body 1.02x0.51mm, IPC Medium Density"
  rect 0.6x0.65 smd: 1(-0.55,0) 2(0.55,0)
  silkscreen extent -1.06,-0.5 1.05,0.5, body extent -0.5,-0.26 0.5,0.26, height 0.52
XTAL/2016 [mm]
  rect 0.85x0.75 smd: 1(0,0) 2(1.35,0) 3(1.35,1.05) 4(0,1.05)
  silkscreen extent -0.33,-0.57 1.68,1.33, body extent -0.32,-0.27 1.68,1.33, height 0.7

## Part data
C1 C2 C3 C4 C5 C6 C7 C8 C9 C10 C11 C12 C13 C14 C15 C16 C17 C18 C19 C20 C21 C22 C23 C24 C25 C26 C27 C28 C29 C30 C31 C32 C33 C34 C35 C36 C37 C38: "Capacitor (Semiconductor SIM Model)"
D3 D4: library part "TVS Diode_BI", "TVS Diode Bi-Directional"
D5: library part ONSC-K1A2-2, "Transient Voltage Suppressor, Micro-Packaged Diode for ESD Protection, 2-Pin SOD-523, Pb-Free, Tape and Reel", Manufacturer="On Semiconductor"
D6: library part LED2, "Typical RED, GREEN, YELLOW, AMBER GaAs LED"
J1: library part e7c17a616881a82b79941196b4bec10, "CONN RCPT USB2.0 TYPEC 5A", Current Rating=5/6.25/1.25/0.25A, Manufacturer=GCT, Package=0, Temperature="-40°C to +85°C", Temperature Range High=+85°C, Temperature Range Low=-40°C, Voltage Rating=20V
L1: "Inductor for Power Circuit, 2.2 uH, +/- 20%, -40 to 105 degC, 2-Pin SMD, RoHS, Tape and Reel", Tolerance=20%
L2 L3 L4 L5: library part INDUCTOR1, "SMD Ferrite Bead"
L6: library part FB0402-120R@100M-500mA, "Ferrite Bead", Manufacturer=Murata, Manufacturer Part Number=BLM15AG121SN1D, Part number IPS=00000009954, Supplier Part Number 1=490-1005-1-ND
MT1 MT2 MT3: library part "Mount Bolt"
P1: library part "Header 6", "Header, 6-Pin"
P2: library part "Header 5", "Header, 5-Pin"
P3: library part "Header 8", "Header, 8-Pin"
R1 R2 R3 R4 R5 R6 R7 R8 R9 R10: "Resistor"
U2: "Step-Down DC-DC Converter with Integrated Low Dropout Regulator and Startup Mode, 9-pin Micro SMD, Pb-Free", Manufacturer="Texas Instruments", PackageTopMarking="XV*I SB", PowerWise=N
U3: "32-bit PSoC 6 Arm Cortex-M4/M0+ MCU", Manufacturer="Infineon Technologies"
U4: Manufacturer="Infineon Technologies", Package Description="BGA,0.50mm pitch,rect.;38 pin,8 columns X 12 rows,4.30mm X 6.05mm X 0.91mm H", Package Reference=PG-VF2BGA-38-1
Y1: library part 801566, "Crystal, Automotive & Industrial Grade Ceramic Base SMD", Manufacturer="Abracon Corporation", Package Description="Crystal; 3.2mm W X 2.5mm L X 0.8mm H body", Supplier Part Number 1=3819746, Temperature Max=125, Temperature Min=-40, Temperature Range=Automotive, Tolerance Neg=-20%, Tolerance Pos=20%, Voltage DC (max)=na

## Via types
v1: diameter 0.4, hole 0.2, Top Layer to Layer 1, tented both sides, 192 vias
v2: diameter 0.5, hole 0.3, Top Layer to Bottom Layer, tented both sides, 162 vias
v3: diameter 0.35, hole 0.2, Top Layer to Bottom Layer, tented both sides, 3 vias

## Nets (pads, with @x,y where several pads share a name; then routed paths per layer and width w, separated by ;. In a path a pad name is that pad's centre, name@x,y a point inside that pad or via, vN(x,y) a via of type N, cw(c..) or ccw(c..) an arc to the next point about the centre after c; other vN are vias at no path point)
1V2_EN: R10.1 U2.B2 U2.C3 U3.59 | length 23.7
  Layer 2 w0.15: v2(4.3,7.381) 4.319,7.4 4.319,9.227 v2(5.492,10.4) ; v2(7.104,25.857) 7.037,25.79 7.037,25.459 6.675,25.097 6.675,17.425 7.35,16.75 7.35,13.531 v2(7.676,13.205)
  Bottom Layer w0.15: U2.C3 4.3,6.97 4.77,6.5 U2.B2 ; U2.C3 v2(4.3,7.381) ; v2(5.492,10.4) 6.418,10.4 6.925,10.907 6.925,11.227 6.975,11.277 6.975,11.597 7.2,11.822 7.2,12.768 7.637,13.205 8.205,13.205 R10.1 ; U3.59 7.085,26.715 7.085,25.877 v2(7.104,25.857)
GND: C1.1 C2.1 C3.1 C4.1 C5.1 C6.1 C7.1 C8.1 C9.1 C10.1 C11.1 C12.1 C13.1 C14.1 C15.1 C16.1 C17.1 C18.1 C19.1 C20.1 C21.1 C22.1 C23.1 C24.1 C25.1 C26.1 C27.1 C28.1 C29.1 C30.1 C31.1 C32.1 C33.1 C34.1 C35.1 C36.1 C37.1 C38.1 D3.1 D4.1 D5.2 J1. J1.A1-B12 J1.A8 J1.B1-A12 J1.B8 MT1.1 MT2.1 MT3.1 P1.2 P1.H P2.5 P3.2 R1.2 R4.2 R6.2 R8.2 R10.2 U1.4 U1.7 U2.A1 U2.A2 U3.2 U3.3 U3.4 U3.5 U3.6 U3.7 U3.10 U3.21 U3.27 U3.28 U3.29 U3.30 U3.31 U3.32 U3.37 U3.38 U3.39 U3.40 U3.41 U3.43 U3.44 U3.45 U3.46 U3.47 U3.49 U3.50 U3.51 U3.52 U3.53 U3.54 U3.55 U3.56 U3.60 U3.65 U3.66 U3.69 U4.A1 U4.A4 U4.A5 U4.A6 U4.A7 U4.A8 U4.B7 U4.B8 U4.C8 U4.D8 U4.H U4.H8 U4.J8 U4.K1 U4.K8 U4.L8 U4.M1 U4.M3 U4.M7 U4.M8 Y1.2 Y1.4 | length 58.1
  Top Layer w0.2: v2(13.625,12.979) 13.683,12.922 13.683,12.627 13.959,12.35 13.998,12.35 14.098,12.25 U4.M1
  Top Layer w0.25: v2(13.82,18.41) 13.82,18.343 14.075,18.088 14.075,17.983 14.115,17.942 14.115,17.76 U4.A1
  Top Layer w0.254: U4.K1 14.941,13.25 15.125,13.066 U4.M3 ; U4.A4 15.625,17.762 15.817,17.954 15.817,18.049 v2(15.864,18.096) ; v2(16.07,17.293) 16.117,17.34 16.117,17.48 16.375,17.738 U4.A5 ; v2(16.85,17.325) 16.875,17.35 U4.A6 ; v2(17.291,13.725) 17.308,13.741 17.866,13.741 U4.J8 U4.H8 ; U4.M7 U4.M8 U4.L8 ; U4.B7 U4.B8 ; U4.A7 U4.A8 U4.B8 ; U4.K8 U4.L8 ; U4.D8 U4.C8 U4.B8 ; v2(18.225,17.25) U4.B8 ; v2(18.396,12.79) 18.365,12.759 17.884,12.759 U4.L8 ; U4.H@19.3,14.25 v1(19.4,14.15)
  Top Layer w0.3: v2(13.625,12.979) 13.679,12.979 13.775,13.075 13.778,13.075 13.953,13.25 U4.K1
  Bottom Layer w0.2: U2.A2 U2.A1 v2(5.675,6) ; U3.69 7.865,22.4 U3.10 ; U3.60 7.475,26.725 7.475,26.248 7.604,26.118 7.604,24.846 v2(8,24.45) ; v2(18.725,15.05) 18.778,14.997 18.778,14.618 18.75,14.589 C13.1
  Bottom Layer w0.254: U3.56 5.865,27.49 v2(5.875,27.5) ; U3.21 9.465,19.676 9.614,19.825 9.775,19.825 ; v2(15.45,15.2) C18.1 ; v2(15.527,15.924) 15.574,15.971 15.977,15.971 16.1,16.094 C17.1 ; C12.1 C15.1 C9.1@15.8,14.325 ; C9.1 C9.1@15.8,14.325 ; v2(17.291,13.725) 17.225,13.725 17.173,13.777 16.923,13.777 C16.1 16.694,14.006 16.119,14.006 C9.1@15.8,14.325 ; J1.A8 23.82,23.895 24.175,24.25
  Bottom Layer w0.3: C37.1 v2(2.9,17) ; C14.1 13.3,12.6 13.625,12.925 v2(13.625,12.979) ; 14.275,10.325 14.275,10.324 14.375,10.224 15.15,10.224 C36.1@15.15,10.024 ; C36.1 Y1.2@16.576,10.124 ; v2(17.961,11.639) 17.968,11.632 17.968,11.032 Y1.4 19.25,11.025 C35.1@19.3,10.975
  Bottom Layer w0.4: v2(4.899,13.066) 4.907,13.058 5.342,13.058 U1.4
  Bottom Layer w0.5: v2(0.7,18.8) C22.1 ; v2(0.7,19.7) C21.1 ; v2(0.7,20.6) C30.1 ; v2(0.7,22.4) R8.2 ; v2(0.7,24.8) C29.1 ; C4.1 1.425,7.121 v2(1.425,6.2) ; v2(3.05,11.325) C1.1@3.582,11.325 ; C3.1 4.6,13.975 4.899,13.676 v2(4.899,13.066) ; C2.1 v2(7.976,14.5) ; v2(7.6,9.45) 8.2,9.45 C6.1 ; C19.1 v2(7.9,29.4) ; C33.1 8.75,16.4 8.758,16.408 v2(9.225,16.408) ; C20.1 v2(8.8,29.4) ; v2@9.225,16.4 C34.1 ; R10.2 9.3,13.85 v2(9.325,13.875) ; v2(9.7,29.4) 9.75,29.35 9.75,28.9 C26.1 ; C8.1 v2(10.9,29.4) ; C25.1 v2(12.1,29.45) ; C32.1 C31.1 v2(14.8,23.2) ; C28.1 v2(14.3,24.1) ; C27.1 v2(14.2,25) ; C23.1 13.8,26.844 v2(14.454,26.844) 14.794,26.844 15.2,27.25 R6.2 ; C24.1 v2(14.4,25.9) ; v2(14.075,28.675) 14.675,28.675 14.8,28.55 C7.1 ; D4.1 16,22.85 v2(16,23.525) ; J1.A1-B12 19.35,22.925 19.35,21.375 19.9,21.375 R1.2 ; v2(23.489,20.485) 23.504,20.5 R4.2 ; J1.B1-A12 25.77,22.67 26.131,22.309 v2(26.131,22.054) ; D5.2 27.111,21 v2(27.13,21.019) v2@27.13,21.022
  Bottom Layer w0.635: v2(17.826,5.568) 17.842,5.584 17.842,6.742 P1.2
  other v1: 10.05,8.2 10.9,8.2 11.75,8.2 12.6,8.2 13.45,8.2 14.3,8.2 15.15,8.2 16,8.2 16.85,8.2 17.7,8.2 18.55,8.2 19.4,8.2 20.25,8.2 21.1,8.2 21.95,8.2 10.05,9.05 10.9,9.05 11.75,9.05 12.6,9.05 13.45,9.05 14.3,9.05 15.15,9.05 16,9.05 16.85,9.05 17.7,9.05 18.55,9.05 19.4,9.05 20.25,9.05 21.1,9.05 21.95,9.05 10.05,9.9 10.9,9.9 11.75,9.9 12.6,9.9 13.45,9.9 14.3,9.9 15.15,9.9 16,9.9 16.85,9.9 17.7,9.9 18.55,9.9 19.4,9.9 20.25,9.9 21.1,9.9 21.95,9.9 10.05,10.75 10.9,10.75 11.75,10.75 12.6,10.75 13.45,10.75 14.3,10.75 15.15,10.75 16,10.75 16.85,10.75 17.7,10.75 18.58,10.737 19.4,10.75 20.25,10.75 21.1,10.75 21.95,10.75 10.05,11.6 10.9,11.6 11.75,11.6 12.6,11.6 19.4,11.6 20.25,11.6 21.1,11.6 21.95,11.6 10.05,12.45 10.9,12.45 11.75,12.45 12.6,12.45 19.4,12.45 20.25,12.45 21.1,12.45 21.95,12.45 10.05,13.3 10.9,13.3 11.75,13.3 12.6,13.3 19.4,13.3 20.25,13.3 21.1,13.3 21.95,13.3 10.05,14.15 10.9,14.15 11.75,14.15 12.6,14.15 20.25,14.15 21.1,14.15 21.95,14.15 10.05,15 10.9,15 11.75,15 12.6,15 19.4,15 20.25,15 21.1,15 21.95,15 10.05,15.85 10.9,15.85 11.75,15.85 12.6,15.85 19.4,15.85 20.25,15.85 21.1,15.85 21.95,15.85 10.05,16.7 10.9,16.7 11.75,16.7 12.6,16.7 19.4,16.7 20.25,16.7 21.1,16.7 21.95,16.7 10.05,17.55 10.9,17.55 11.75,17.55 12.6,17.55 19.4,17.55 20.25,17.55 21.1,17.55 21.95,17.55 10.05,18.4 10.9,18.4 11.75,18.4 12.6,18.4 19.4,18.4 20.25,18.4 21.1,18.4 21.95,18.4 10.05,19.25 10.9,19.25 11.75,19.25 12.6,19.25 13.45,19.25 14.3,19.25 15.15,19.25 16,19.25 16.85,19.25 17.7,19.25 18.55,19.25 19.4,19.25 20.25,19.25 21.1,19.25 21.95,19.25 10.05,20.1 10.9,20.1 11.75,20.1 12.6,20.1 13.45,20.1 14.3,20.1 15.15,20.1 16,20.1 16.85,20.1 17.7,20.1 18.55,20.1 19.4,20.1 20.25,20.1 21.1,20.1 21.95,20.1 10.05,20.95 10.9,20.95 11.75,20.95 12.6,20.95 13.45,20.95 14.3,20.95 15.15,20.95 16,20.95 16.85,20.95 17.7,20.95 18.55,20.95 19.4,20.95 20.25,20.95 21.1,20.95 21.95,20.95 10.05,21.8 10.9,21.8 11.75,21.8 12.6,21.8 13.45,21.8 14.3,21.8 15.15,21.8 16,21.8 16.85,21.8 17.7,21.8 18.55,21.8 19.4,21.8 20.25,21.8 21.1,21.8 21.95,21.8
  other v2: 6,2 8,2 12,2 14,2 16,2 18,2 20,2 24,2 26,2 20,4 24,4 26,4 28,4 28,8 24,10 28,10 24,12 24,14 24,16 24,18 28,20 5.25,20.5 8,20.75 8.75,20.75 5.25,21.25 8,21.5 8.75,21.5 5.25,22 28,22 8,22.25 8.75,22.25 5.25,22.75 8,23 8.75,23 9.5,23 5.25,23.5 8,23.75 8.75,23.75 9.5,23.75 5.25,24.25 8.75,24.412 9.5,24.457 5.25,25 2,26 16,26 28,26 2,28 4,28
  other v3: 5.196,12.073 5.791,12.058 6.325,12.075
GPIO1: P3.7 U3.62 | length 27.8
  Layer 2 w0.15: v2(8.104,25.75) 8.199,25.75 8.374,25.575 8.471,25.575 8.509,25.537 8.896,25.537 9.2,25.842 9.2,27.2 9.975,27.975 12.997,27.975 13.072,27.9 15.4,27.9 17.4,25.9 26.376,25.9 28.1,24.176 28.1,22.99 P3.7
  Bottom Layer w0.15: v2(8.104,25.75) 8.171,25.817 8.171,26.199 8.23,26.258 8.23,26.7 U3.62
GPIO2: P3.8 U3.63 | length 25
  Layer 2 w0.15: v2(8.699,26.012) 8.705,26.019 8.705,27.13 9.851,28.275 13.121,28.275 13.196,28.2 15.7,28.2 17.7,26.2 26.5,26.2 28.475,24.225 29.405,24.225 P3.8
  Bottom Layer w0.15: U3.63 8.682,26.718 8.682,26.029 v2(8.699,26.012)
LED: D6.2 U3.61 | length 19.6
  Top Layer w0.15: v2(3.598,15.3) 3.614,15.317 3.614,15.564 3.75,15.7 D6.2
  Layer 2 w0.15: v2(3.598,15.3) 4.148,15.85 4.375,15.85 6.075,17.55 6.075,24.897 5.2,25.772 5.2,26.58 5.013,26.767 5.013,28.35 v2(4.95,28.413)
  Bottom Layer w0.15: v2(4.95,28.413) 5.013,28.35 6.103,28.35 7.063,27.39 7.652,27.39 7.865,27.177 U3.61
MCU_RSTn: C37.2 P1.4 P2.4 P3.4 R5.2 U3.8 | length 61.4
  Layer 1 w0.15: v2(6,16.76) 6,19.474 6.751,20.225 8.975,20.225 9.313,20.563 9.313,21.913 9.758,22.358 9.864,22.358 10.475,22.969 v2(10.475,22.975)
  Layer 2 w0.15: v2(6,16.76) 6.004,16.76 6.75,16.013 6.75,11.104 10.348,7.505 10.348,5.752 11.775,4.325 14.875,4.325 15.4,4.85 v2(15.4,4.897)
  Bottom Layer w0.15: R5.2 C37.2 1.3,16.475 ; P2.4 0.9,11.87 0.9,15.861 1.3,16.261 1.3,16.475 ; v2(6,16.76) 5.905,16.76 5.735,16.589 5.728,16.589 5.564,16.425 1.35,16.425 1.3,16.475 ; v2(10.475,22.975) 10.52,22.975 10.745,23.2 U3.8 ; P1.4 15.375,8.139 15.636,8.4 24,8.4 29.47,13.87 P3.4 ; v2(15.4,4.897) P1.4@15.4,6.55
MMIC_CLK: U3.16 U4.B2 | length 6.8
  Top Layer w0.15: U4.B2 14.638,17.237 15.388,17.237 v2(15.4,17.225)
  Bottom Layer w0.15: U3.16 12.101,20 13.025,19.076 13.025,17.597 13.268,17.354 15.177,17.354 15.305,17.225 v2(15.4,17.225)
MMIC_CSn: U3.17 U4.E1 | length 6.9
  Top Layer w0.15: U4.E1 14.151,15.724 14.804,15.724 v2(14.829,15.699)
  Bottom Layer w0.15: U3.17 12.076,19.6 12.725,18.951 12.725,16.978 14.004,15.699 14.699,15.699 v2@14.75,15.75
MMIC_DIO2: U3.23 U4.C1 | length 7.7
  Top Layer w0.15: v2(13.6,16.775) 13.613,16.762 14.113,16.762 U4.C1
  Layer 2 w0.15: v2(8.665,19.554) 8.665,18.935 9.181,18.419 11.572,18.419 13.217,16.775 v2(13.6,16.775)
  Bottom Layer w0.15: U3.23 v2(8.665,19.554)
MMIC_DIO3: U3.24 U4.D1 | length 8
  Top Layer w0.15: U4.D1 14.138,16.237 14.429,16.237 v2(14.441,16.225)
  Layer 2 w0.15: v2(8.435,18.061) 8.493,18.119 11.406,18.119 13.3,16.225 v2(14.441,16.225)
  Bottom Layer w0.15: U3.24 8.3,18.83 8.3,18.291 8.435,18.156 v2(8.435,18.061)
MMIC_DIO4_IRQ: U3.18 U4.G1 | length 6.7
  Top Layer w0.15: U4.G1 14.155,14.75 14.413,15.008 14.579,15.008 v2(14.646,15.075)
  Bottom Layer w0.15: U3.18 10.654,18.854 10.654,18.046 11.103,17.597 11.682,17.597 14.171,15.108 14.614,15.108 v2(14.646,15.075)
MMIC_DIO5: U3.20 U4.H1 | length 6.8
  Top Layer w0.15: v2(13.376,14.313) 13.41,14.279 14.096,14.279 U4.H1
  Bottom Layer w0.15: U3.20 9.865,17.986 13.068,14.783 13.068,14.677 13.376,14.37 v2(13.376,14.313)
MMIC_MISO: U3.15 U4.B1 | length 4.7
  Top Layer w0.15: v2(13.525,17.829) 13.525,17.82 14.095,17.25 U4.B1
  Bottom Layer w0.15: U3.15 12.125,20.4 13.35,19.175 13.35,18.612 13.345,18.607 13.345,18.103 13.525,17.923 v2(13.525,17.829)
MMIC_MOSI: U3.14 U4.A3 | length 5.9
  Top Layer w0.15: U4.A3 15.125,18.179 15.375,18.429 v2(15.375,18.524)
  Bottom Layer w0.15: U3.14 12.207,20.8 13.807,19.2 14.925,19.2 14.95,19.175 14.964,19.175 15.125,19.014 15.125,18.845 15.375,18.595 v2(15.375,18.524)
MMIC_RSTn: U3.19 U4.F1 | length 6
  Top Layer w0.15: v2(13.412,15.195) 13.439,15.223 14.098,15.223 U4.F1
  Bottom Layer w0.15: U3.19 10.291,18.839 10.291,17.985 11.068,17.208 11.542,17.208 13.297,15.453 13.297,15.404 13.412,15.29 v2(13.412,15.195)
MMIC_XI: C35.2 U4.M5 Y1.1 | length 4.7
  Top Layer w0.15: U4.M5 16.403,12.222 16.403,11.954 v2(16.43,11.927)
  Bottom Layer w0.15: v2(16.43,11.927) 16.494,11.863 16.905,11.863 17.3,11.468 17.3,10.582 17.457,10.425 17.475,10.425 17.925,9.975 Y1.1 17.989,9.989 19.314,9.989 C35.2
MMIC_XO: C36.2 U4.M4 Y1.3 | length 2.6
  Top Layer w0.15: v2(15.5,11.837) 15.5,11.932 15.596,12.028 15.596,12.221 U4.M4
  Bottom Layer w0.15: v2(15.5,11.837) 15.5,11.788 15.3,11.588 C36.2 15.399,11.025 Y1.3
NetC7_2: C7.2 J1.1 J1.2 J1.3 J1.4 R6.1 | length 17
  Bottom Layer w1: J1.2 J1.1 J1.4 J1.3
NetC8_2: C8.2 U3.67 | length 1.5
  Bottom Layer w0.15: U3.67 10.3,26.77 10.3,27.35 10.85,27.9 C8.2
NetD6_1: D6.1 R9.2 | length 1.9
  Top Layer w0.15: v2(3.572,13.175) 3.638,13.242 3.638,13.513 D6.1
  Bottom Layer w0.15: v2(3.572,13.175) R9.2
NetJ1_A5: J1.A5 R1.1 | length 1.8
  Bottom Layer w0.15: R1.1 20.9,21.375 21.32,21.795 J1.A5
NetJ1_B5: J1.B5 R4.1 | length 1.6
  Bottom Layer w0.15: R4.1 24.05,21.5 24.32,21.77 J1.B5
NetL1_1: L1.1 U2.B1 | length 3.1
  Bottom Layer w0.3: U2.B1 4.8,5.601 4.976,5.425 6.753,5.425 L1.1
NetR7_2: R7.2 R8.1 U3.42 | length 21
  Layer 2 w0.15: v2(1.1,21.5) 1.318,21.282 1.318,16.303 0.85,15.835 0.85,8.725 2.596,6.979 3.657,6.979
  Bottom Layer w0.15: R7.2@1.098,23.398 1.098,23.352 1.825,22.625 2.025,22.625 2.2,22.45 R8.1 ; v2(1.1,21.5) 1.148,21.548 1.398,21.548 2.2,22.35 R8.1 ; U3.42 R8.1
SWCLK: P2.3 U3.34 | length 10.2
  Layer 2 w0.15: P2.3 3.097,13.136 3.097,15.471 3.776,16.15 4.251,16.15 5.544,17.443 5.544,18.273 5.307,18.51 4.607,18.51 4.297,18.2 v2(4.245,18.2)
  Bottom Layer w0.15: v2(4.245,18.2) 4.255,18.21 4.255,18.855 U3.34
SWDIO: P2.2 U3.33 | length 7.5
  Layer 2 w0.15: P2.2 2.191,13.31 2.797,13.915 2.797,15.245 2.773,15.269 2.773,15.571 3.751,16.55 4.226,16.55 5.225,17.548 5.225,17.779 5.136,17.868 5.136,17.968 v2(5.069,18.035)
  Bottom Layer w0.15: U3.33 4.7,18.83 4.7,18.388 5.053,18.035 v2(5.069,18.035)
UART_RX: P1.6 P3.6 U3.25 | length 43.1
  Layer 2 w0.15: v2(7.875,19.7) 7.875,17.949 8.157,17.668 8.157,16.189 8.751,15.595 8.751,13.061 8.4,12.71 8.4,10.726 11.248,7.878 11.248,6.402 12.175,5.475 12.85,5.475 v2(12.9,5.425)
  Bottom Layer w0.15: U3.25 7.87,18.87 7.87,19.695 v2(7.875,19.7) ; P1.6@12.8,7.609 12.8,7.985 13.815,9 23.751,9 28.1,13.349 28.1,17.45 P3.6 ; v2(12.9,5.425) P1.6@12.9,6.525
UART_TX: P1.5 P3.5 U3.26 | length 41.2
  Layer 2 w0.15: v2(7.4,18.053) 7.4,18 7.857,17.543 7.857,16.041 8.451,15.447 8.451,13.186 8.375,13.11 8.1,12.835 8.1,10.602 8.375,10.327 10.948,7.754 10.948,6.177 12.2,4.925 13.853,4.925 14.153,5.225 v2(14.225,5.225)
  Bottom Layer w0.15: v2(7.4,18.053) 7.432,18.086 7.432,18.832 U3.26 ; P1.5 14.125,7.997 14.828,8.7 23.876,8.7 28.4,13.224 28.4,15.21 P3.5 ; P1.5@14.15,6.675 14.225,6.6 v2(14.225,5.225)
USB_N: D4.2 J1.A7 J1.B7 R3.1 | length 17
  Layer 1 w0.152: v2(21.275,24.8) 21.369,24.8 21.51,24.941 22.537,24.941 22.649,24.83 22.649,24.326 v2(22.7,24.275)
  Bottom Layer w0.165: R3.1 14.667,21.4 14.667,21.368 14.764,21.271 15.496,21.271 15.95,21.725 D4.2 16,21.725 16.217,21.508 16.217,21.431 16.314,21.334 17.417,21.334 17.843,20.908 17.843,20.725 18.443,20.125 21.575,20.125 22.125,20.675 22.125,21.409 21.899,21.635 21.899,22.356 21.887,22.367 21.887,22.878 J1.B7 21.81,22.955 21.81,24.465 21.539,24.736 21.339,24.736 v2(21.275,24.8) ; v2(22.7,24.275) 22.75,24.225 22.75,23.534 22.753,23.532 22.753,23.012 J1.A7
USB_P: D3.2 J1.A6 J1.B6 R2.1 | length 19.1
  Layer 1 w0.152: v2(21.275,25.4) 21.369,25.4 21.51,25.259 22.669,25.259 23.018,24.91 23.018,24.651 23.3,24.369 v2(23.3,24.275)
  Bottom Layer w0.165: R2.1 14.667,20.667 14.667,20.809 14.764,20.906 14.802,20.906 14.824,20.929 15.621,20.929 15.95,20.6 16,20.6 16.217,20.817 16.217,20.894 16.314,20.991 17.275,20.991 17.5,20.766 17.5,20.583 18.301,19.782 21.717,19.782 22.468,20.533 22.468,21.551 22.241,21.777 22.241,22.356 22.253,22.367 22.253,22.878 22.387,23.012 22.387,23.532 22.39,23.534 22.39,23.858 22.153,24.096 22.153,24.613 21.366,25.4 v2(21.275,25.4) ; v2(23.3,24.275) 23.31,24.265 23.31,22.955 J1.B6
USBD_N: R3.2 U3.12 | length 2.4
  Bottom Layer w0.165: U3.12 11.427,21.573 11.802,21.573 11.803,21.571 12.534,21.571 12.928,21.177 13.236,21.177 13.242,21.183 13.333,21.183 13.5,21.35 R3.2
USBD_P: R2.2 U3.13 | length 2.4
  Bottom Layer w0.165: U3.13 11.427,21.227 11.802,21.227 11.803,21.229 12.391,21.229 12.801,20.819 13.181,20.819 13.283,20.717 13.333,20.717 13.5,20.55 R2.2
USER_IO: P1.3 P3.3 U3.57 | length 46
  Layer 2 w0.15: v2(5.858,25.838) 6.375,25.32 6.375,17.301 7.05,16.626 7.05,11.228 10.648,7.63 10.648,5.977 12,4.625 14.45,4.625 15.25,5.425 v2(16.6,5.425)
  Bottom Layer w0.15: v2(5.858,25.838) 6.23,26.21 6.23,26.7 U3.57 ; v2(16.6,5.425) P1.3@16.6,6.45 ; P1.3 16.625,7.324 17.376,8.075 24.123,8.075 27.378,11.33 P3.3
VCC_1V2R: C6.2 C9.2 C10.2 C15.2 C16.2 C17.2 C18.2 U2.A3 U4.E8 U4.F8 U4.J1 U4.M6 | length 27.1
  Top Layer w0.3: v2(13.55,13.625) 13.604,13.625 13.729,13.75 U4.J1 ; U4.M6 16.875,12.665 17.231,13.021 v2(17.231,13.075) ; v2(17.475,15.872) 17.529,15.872 17.652,15.75 U4.E8 ; v2(17.526,15.242) 17.534,15.25 U4.F8
  Layer 1 w0.5: v2(13.55,13.625) 13.588,13.663 13.618,13.693 16.168,13.693 16.22,13.745 ; v2(17.231,13.075) 16.889,13.075 16.22,13.745 ; v2(17.475,15.872) 17.526,15.821 v2(17.526,15.242) ; v2@17.503,15.198 16.578,15.198 16.285,14.906 16.285,13.81 16.22,13.745
  Layer 2 w0.4: v2(5.42,7.57) 5.42,8.993 5.75,9.323 v2(5.75,9.35)
  Layer 2 w0.5: v2(9.175,12.3) 10.175,12.3 11.5,13.625 v2(13.55,13.625)
  Bottom Layer w0.3: U2.A3 5.382,7.082 5.382,7.532 v2(5.42,7.57) ; v2(5.75,9.35) 5.788,9.388 6.538,9.388 C6.2 ; v2(13.55,13.625) 13.588,13.587 14.713,13.587 C15.2 C9.2 ; C16.2 C16.2@16.862,12.838 ; C18.2 C17.2 ; C18.2@17.1,15.25 17.437,15.587 17.437,15.834 v2(17.475,15.872) 17.529,15.872 17.638,15.764 18.112,15.764 C10.2
  Bottom Layer w0.5: C6.2 6.65,9.6 7.875,10.825 7.875,11.825 8.35,12.3 v2(9.175,12.3)
VCC_1V8M: C3.2 L5.1 U1.5 | length 5.8
  Layer 2 w0.5: v2(5.623,13.971) 5.623,15.812 v2(5.925,16.114)
  Bottom Layer w0.254: v2@5.607,13.927 5.85,13.685 U1.5
  Bottom Layer w0.4: v2@5.607,13.927 C3.2@5.607,14.493 ; v2(5.925,16.114) 5.932,16.121 6.759,16.121 6.988,16.35 7.75,16.35 L5.1
VCC_1V8MM: C33.2 C34.2 L5.2 U3.22 | length 3.4
  Bottom Layer w0.2: C33.2 8.75,17.4 9.065,17.715 U3.22
  Bottom Layer w0.5: L5.2 8.65,17.4 8.75,17.4 C34.2
VCC_1V8R: C5.2 C11.2 L1.2 L6.2 U2.B3 U2.C2 U4.A2 | length 40.9
  Top Layer w0.3: v2(14.6,18.2) 14.625,18.175 U4.A2
  Layer 2 w0.75: v2@9.3,11.4 v2(9.275,11.375) ; v2(14.6,18.2) 14.6,18.956 15.039,19.396 16.117,19.396 16.556,18.956 v2(16.556,18.5) 20.086,18.5 20.525,18.061 20.525,11.6 19.675,10.75 10.35,10.75 ; v2(9.275,11.375) v2(9.275,10.7) 10.3,10.7 10.35,10.75 ; v2(9.275,11.375) 9.725,11.375 10.35,10.75
  Bottom Layer w0.2: 3.9,6.525 3.975,6.525 3.988,6.512 4.288,6.512 U2.C2
  Bottom Layer w0.3: U2.B3 4.85,7.05 4.85,7.609 4.837,7.622 4.837,7.712 ; v2(16.556,18.5) L6.2
  Bottom Layer w0.4: 3.9,6.525 3.7,6.725 3.7,7.728 3.997,8.025 4.524,8.025 4.787,7.761 ; 4.837,7.712 4.787,7.761 ; L1.2 6.828,8.3 5.084,8.3 4.85,8.066 4.85,7.824 4.787,7.761
  Bottom Layer w0.5: L1.2 7.314,7.814 9.286,7.814 C5.2
  Bottom Layer w0.75: v2(9.275,10.7) 9.4,10.575 C5.2
VCC_1V8RF: C12.2 C13.2 C14.2 C38.2 L6.1 U4.G8 U4.L1 U4.M2 | length 17.3
  Top Layer w0.3: U4.L1 14.425,12.75 14.625,12.55 U4.M2 14.625,12.022 14.523,11.919 v2(14.523,11.865) ; v2(17.39,14.509) 17.444,14.509 17.627,14.692 17.681,14.692 17.687,14.698 17.74,14.698 17.741,14.7 17.762,14.7 17.812,14.75 U4.G8
  Layer 1 w0.305: v2(14.523,11.865) 15.135,11.252 16.208,11.252 16.213,11.248 16.637,11.248 16.642,11.252 16.792,11.252 17.844,12.304 17.844,14.002 17.39,14.456 v2(17.39,14.509)
  Bottom Layer w0.3: C14.2 14.4,11.5 14.4,11.688 14.523,11.811 14.523,11.919 14.7,12.097 14.7,12.525 C12.2
  Bottom Layer w0.5: v2(17.39,14.509) C13.2 C13.2
  Bottom Layer w0.508: C13.2 17.836,14.504 17.836,14.106 18.191,13.75 19.188,13.75 19.486,14.048 19.486,15.814 C38.2 19.45,17.225 18.846,17.829 18.846,18.354 L6.1
VCC_3V3M: C2.2 L2.1 L3.1 L4.1 P2.1 R9.1 U1.6 | length 10.5
  Bottom Layer w0.3: P2.1 2.418,14.162 2.761,14.162 2.95,13.973 2.95,12.588 3.363,12.175 R9.1
  Bottom Layer w0.5: P2.1 2,15.4 2.5,15.9 2.9,15.9 2.95,15.95 4.317,15.95 4.367,15.9 4.417,15.95 5.1,15.95 5.15,15.9 L4.1 ; L4.1@5.25,15.9 5.25,15.869 5.669,15.45 6.4,15.45 C2.2@6.4,14.55
VCC_3V3MA: C29.2 C30.2 L4.2 U3.36 U3.48 | length 13.5
  Layer 2 w0.5: v2(2.2,24.1) v2(2.2,21.2) 2.9,21.2 3.6,20.5 3.6,18.474 3.595,18.469 3.595,17.905 v2(3.9,17.6)
  Bottom Layer w0.152: C29.2 U3.48 ; 3.1,20 U3.36
  Bottom Layer w0.254: C30.2@2.2,20.554 2.323,20.431 2.583,20.431 3.001,20.013 3.087,20.013 3.089,20.011
  Bottom Layer w0.5: C30.2 v2(2.2,21.2) ; v2(2.2,24.1) C29.2 ; v2(3.9,17.6) 3.95,17.55 4.636,17.55 4.9,17.286 4.9,17.15 5.15,16.9 L4.2
VCC_3V3MM: C19.2 C20.2 C21.2 C22.2 C23.2 C24.2 C25.2 C26.2 C31.2 C32.2 L2.2 R5.1 U3.1 U3.11 U3.35 U3.64 U3.68 | length 38
  Layer 1 w0.5: v2(2.945,18.2) v2(2.945,18.8) 2.945,19.633 4.2,20.888 4.2,26.744 5.606,28.15 6.144,28.15 6.16,28.134 7.277,28.134 v2(7.315,28.096) 9.229,28.096 9.825,27.5 v2(12.8,27.5)
  Layer 2 w0.5: v2@12.225,26.85 12.225,26.025 v2(12.2,26) 12.725,26 13.175,25.55 13.175,24.075 12.55,23.45 v2(12.55,22.575)
  Bottom Layer w0.2: U3.68 10.665,27.055 11.01,27.4 11.55,27.4 12.05,27.9 C25.2
  Bottom Layer w0.254: C21.2 2.304,19.596 3.526,19.596 U3.35 ; C20.2@8.85,27.9 9.065,27.685 U3.64 ; U3.11 12.2,22 12.375,22.175 12.375,22.333 12.55,22.508 v2(12.55,22.575) ; U3.1 v2(12.2,26) ; v2@12.525,22.575 12.572,22.528 12.822,22.528 13.15,22.2 C32.2
  Bottom Layer w0.305: C32.2 C31.2
  Bottom Layer w0.4: v2(12.2,26) C24.2@12.85,26
  Bottom Layer w0.5: v2(7.315,28.096) 7.654,28.096 7.85,27.9 8.067,27.9 8.143,27.976 8.674,27.976 8.75,27.9 9.065,27.9 C26.2 ; C25.2 12.4,27.9 v2(12.8,27.5) C23.2 ; v2(12.2,26.9) 12.25,26.85 C23.2@12.8,26.85
VCC_3V3MN: C27.2 C28.2 L3.2 U3.9 | length 19.8
  Layer 1 w0.5: v2(7.15,19.75) 7.15,19.116 6.582,18.548 6.582,17.418 7.976,16.024 v2(7.976,15.25)
  Layer 2 w0.5: v2(7.15,19.75) 7.15,24.655 7.595,25.1 8.274,25.1 8.312,25.062 9.187,25.062 9.231,25.107 11.063,25.107 11.613,24.557 v2(12.337,24.557)
  Bottom Layer w0.254: U3.9 11.413,22.813 12.043,22.813 12.332,23.102 12.351,23.102 12.5,23.251 12.5,23.6 C28.2@12.7,23.8
  Bottom Layer w0.5: L3.2@7.407,15.393 7.833,15.393 v2(7.976,15.25) ; v2(12.337,24.557) 12.344,24.55 12.8,24.55 ; C28.2 12.8,24.55 ; C27.2 12.8,24.55
VCC_5V: C1.2 C4.2 D5.1 J1.A4-B9 J1.B4-A9 P1.1 P3.1 R7.1 U1.1 U1.2 U1.3 U2.C1 | length 85.5
  Layer 2 w0.2: v2(0.975,24.1) 1.65,23.425 1.65,16.175 1.175,15.7 1.175,9.1 1.943,8.333 v2(2.907,8.333)
  Layer 2 w0.75: v2(20.55,24.075) 20.55,23.189 20.989,22.75 24.25,22.75 v2@25,22
  Layer 2 w1.27: v2@25,22 25.096,21.904 25.096,20.486 25.109,20.473 25.109,9.062 ccw(c27.454,9.062) 25.796,7.404 26.206,6.994 ccw(c28.002,8.79) 28.002,6.25 P3.1
  Bottom Layer w0.2: v2(0.975,24.1) 1,24.1 1.45,24.1 2.1,23.45 R7.1
  Bottom Layer w0.254: 4.075,5.8 4.097,5.8 4.297,6 U2.C1
  Bottom Layer w0.4: J1.A4-B9 20.27,23.045 20.27,23.655 20.355,23.74 20.355,23.853 20.55,24.048 v2(20.55,24.075)
  Bottom Layer w0.5: 4.775,11.1 U1.3 U1.2 U1.1
  Bottom Layer w0.508: 4,5.241 4,5.725 ; J1.B4-A9 25.016,22.899 25.016,22.034 v2(25.025,22.025) 25.14,21.91 D5.1
  Bottom Layer w0.635: 4,5.725 3.811,5.725 3.622,5.725 3.314,6.032 3.299,6.032 2.907,6.424 v2(2.907,8.333) 3.741,9.166 3.741,10.191 4.173,10.191 4.775,10.794 4.775,11.1
  Bottom Layer w1: 3.811,5.241 3.811,5.142 4.378,4.575 8.775,4.575 8.975,4.775 11.925,4.775 12.703,3.997 18.542,3.997 19.43,4.885 19.43,6.675 19.529,6.774 24.226,6.774 24.75,6.25 P3.1
pads on no net: U3.58

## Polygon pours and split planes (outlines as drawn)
VCC_3V3MM on Bottom Layer "NONET_L02_P-001" (solid, shelved, pour order 0): 1.95,19.95 1.8,19.8 1.8,16.9 2.05,16.65 4.45,16.65 4.45,17.45 4,17.9 3.5,17.9 3.3,18.1 3.32,18.12 3.32,19.49 3.21,19.49 3,19.7 2.45,19.7 2.45,19.95
GND on Bottom Layer "NONET_L04_P005" (solid, remove dead copper, shelved, pour order 5): 0,0 0,30 32,30 32,0
GND on Layer 2 "NONET_L03_P008" (solid, shelved, pour order 8): 0,0 0,30 32,30 32,0
GND on Layer 1 "NONET_L02_P007" (solid, shelved, pour order 7): 0,0 0,30 32,30 32,0
GND on Top Layer "NONET_L01_P006" (solid, shelved, pour order 6): 0.227,0.125 0.227,30.125 32.227,30.125 32.227,0.125

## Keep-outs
Keep-Out Layer:
  the board outline again, w0.1

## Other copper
Top Layer:
  pour cut-out: 9.65,22.25 22.4,22.25 22.4,7.8 9.65,7.8
Bottom Layer:
  region net VCC_3V3M: 6.288,12.908 6.296,12.916 6.296,13.733 6.15,13.88 6.15,14.629 6.288,14.767 6.697,14.767 6.856,14.607 6.856,13.868 6.987,13.737 6.987,13.014 6.815,12.843 6.394,12.843
  region net NetC7_2: 16.34,29.4 15.931,28.991 15.931,27.077 16.182,26.825 16.9,26.825 17.713,26.012 18.237,26.012 18.75,26.525 18.75,29.025 18.375,29.4

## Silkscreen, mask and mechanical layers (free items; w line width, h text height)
Top Overlay:
  drawing of 3563 lines, arcs and shapes, not listed
  text "AS-613" at 2.024,22.895 h1.3
  text "202607" at 2.126,21.95 h1
Dimensions:
  text "Layer : 4L" at 10.1,40.558 h3
  text "Thickiness : 1.2mm" at 9.9,37.031 h3

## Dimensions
32,30 to 32,0 on Dimensions
0,30 to 32,30 on Dimensions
